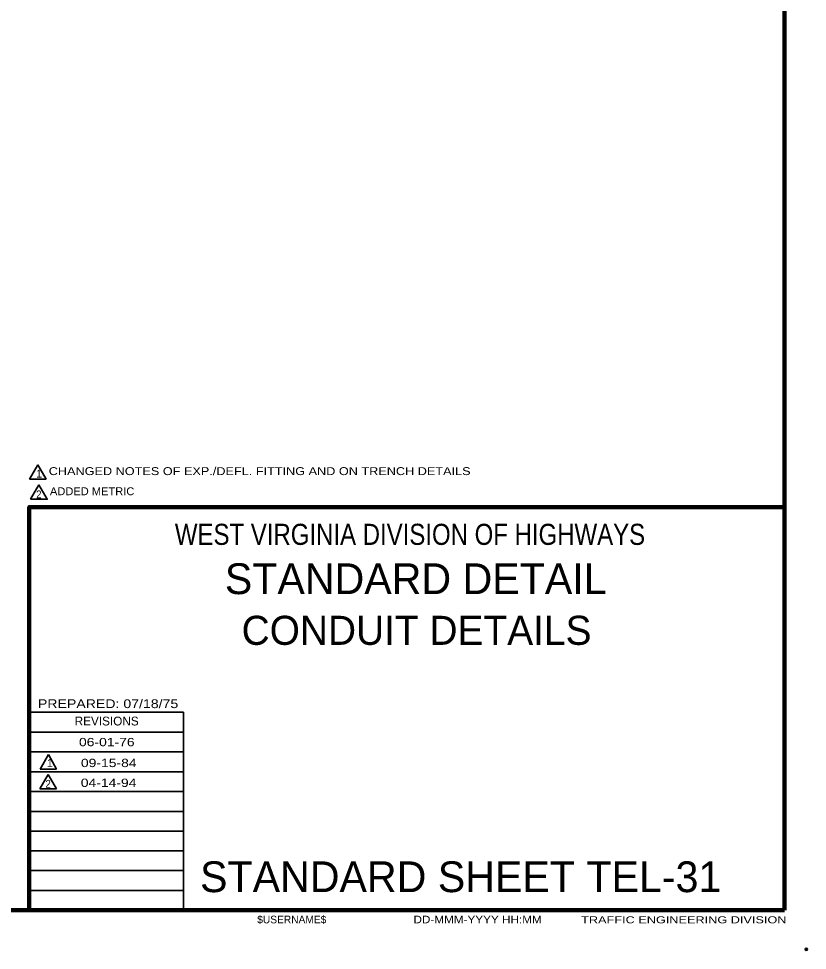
# Model space of a CAD drawing. Extents: x -50 to 806, y -9 to 535.
# Drawn here: x 578.1 to 805.8, y -8.8 to 260 of the extents above; entities that cross this region are included whole.
import ezdxf
from ezdxf.enums import TextEntityAlignment as Align

# ---------------------------------------------------------------- set-up
doc = ezdxf.new("R2010")
doc.units = 0
doc.header["$LTSCALE"] = 1.2
doc.header["$PDMODE"] = 32
doc.header["$PDSIZE"] = 0.6
doc.layers.add('1', color=7, linetype='Continuous', lineweight=35)
doc.layers.add('61', color=7, linetype='Continuous', lineweight=35)

msp = doc.modelspace()

# ---------------------------------------------------------------- linework, layer by layer
at = {"layer": '1', "lineweight": 158}
for q in [(799.155, 528.863), (799.155, 119.063), (7.555, 2.763)]:
    msp.add_line((799.155, 2.763), q, dxfattribs=at)
at = {"layer": '1', "lineweight": 13}
msp.add_line((799.155, 2.763), (799.155, 528.863), dxfattribs=at)
at = {"layer": '1'}
for p, q in [((583.588, 131.27), (581.188, 127.113)), ((583.588, 131.27), (585.988, 127.113)), ((585.988, 127.113), (581.188, 127.113)), ((583.929, 125.465), (581.529, 121.308)), ((625.655, 54.163), (581.155, 54.163)), ((625.655, 48.463), (581.155, 48.463)), ((586.656, 47.647), (584.256, 43.49)), ((586.656, 47.647), (589.056, 43.49)), ((589.056, 43.49), (584.256, 43.49)), ((625.655, 42.663), (581.155, 42.663)), ((586.608, 41.914), (584.208, 37.757)), ((586.608, 41.914), (589.008, 37.757)), ((589.008, 37.757), (584.208, 37.757)), ((625.655, 36.963), (581.155, 36.963)), ((625.655, 31.263), (581.155, 31.263)), ((625.655, 25.563), (581.155, 25.563)), ((625.655, 19.863), (581.155, 19.863)), ((625.655, 14.163), (581.155, 14.163)), ((625.655, 8.463), (581.155, 8.463))]:
    msp.add_line(p, q, dxfattribs=at)
for points in [[(583.929, 125.465), (586.329, 121.308), (581.529, 121.308)], [(625.655, 2.763), (625.655, 59.863), (581.155, 59.863)]]:
    msp.add_lwpolyline(points, dxfattribs=at)
at = {"layer": '1', "lineweight": 158}
msp.add_lwpolyline([(581.155, 2.763), (581.155, 119.063), (799.155, 119.063)], dxfattribs=at)
at = {"layer": '1'}
msp.add_point((805.455, -8.537), dxfattribs=at)
at = {"layer": '61', "lineweight": 53}
for q in [(646.455, 2.763), (646.455, 2.763), (646.455, 2.763), (646.755, 2.763), (646.755, 2.763)]:
    msp.add_line((799.155, 2.763), q, dxfattribs=at)

# ---------------------------------------------------------------- texts
at = {"layer": '1'}
for s, height, p in [('1', 2.28, (583.144, 127.577)), ('REVISIONS', 2.537, (594.255, 56.063)), ('1', 2.28, (586.229, 44.057)), ('STANDARD SHEET TEL-31', 8.881, (630.455, 7.963)), ('$USERNAME$', 2.2, (646.955, -1.037))]:
    msp.add_text(s, height=height, dxfattribs=at).set_placement(p)
for s, height, width, p in [('CHANGED NOTES OF EXP./DEFL. FITTING AND ON TRENCH DETAILS', 2.28, 1.2, (586.773, 128.303)), ('2', 2.28, 0.9, (583.144, 121.601)), ('ADDED METRIC', 2.28, 1.05, (587.114, 122.498)), ('PREPARED: 07/18/75', 2.537, 1.2, (583.655, 61.063)), ('2', 2.28, 0.9, (585.84, 38.068)), ('DD-MMM-YYYY HH:MM', 2.2, 1.15, (692.055, -1.037)), ('TRAFFIC ENGINEERING DIVISION', 2.031, 1.35, (740.455, -1.037))]:
    msp.add_text(s, height=height, dxfattribs=dict(at, width=width)).set_placement(p)
for s, height, width, p in [('WEST VIRGINIA DIVISION OF HIGHWAYS', 6.089, 0.85, (691.055, 108.163)), ('06-01-76', 2.4, 1.25, (603.528, 50.061)), ('09-15-84', 2.4, 1.25, (604.091, 44.048)), ('04-14-94', 2.4, 1.25, (604.052, 38.315))]:
    msp.add_text(s, height=height, dxfattribs=dict(at, width=width)).set_placement(p, align=Align.CENTER)
for s, height, p in [('STANDARD DETAIL', 8.881, (692.705, 93.963)), ('CONDUIT DETAILS', 8.391, (692.946, 79.321))]:
    msp.add_text(s, height=height, dxfattribs=at).set_placement(p, align=Align.CENTER)

doc.saveas('drawing.dxf')
